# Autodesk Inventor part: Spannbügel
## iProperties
Created: 2007-11
Part Number: Spannbügel
Document SubType Name: Modeling
Designer: Benno
Manufacturer: Standard
Standards Organization: Custom
Author: Benno
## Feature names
1. Extrusion1
2. Rundung1 [Fillet]
3. Extrusion2
4. Extrusion3
5. Bohrung1 [Hole]
